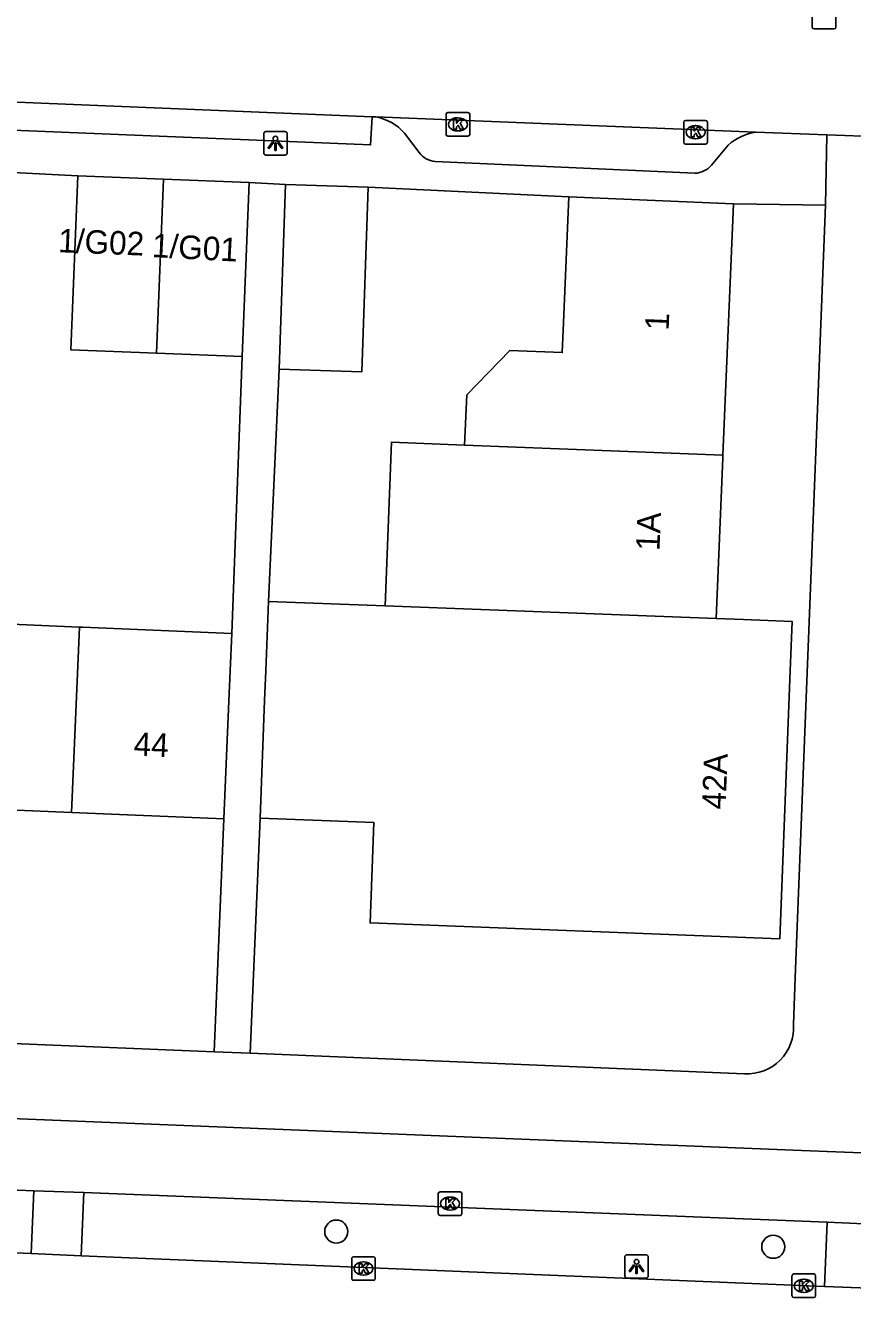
# Model space of a CAD drawing. Extents: x 160732 to 162105, y 387428 to 388479.
# Drawn here: x 161213.7 to 161248.8, y 387473.4 to 387527.4 of the extents above; entities that cross this region are included whole.
import ezdxf

# ---------------------------------------------------------------- set-up
doc = ezdxf.new("R2010")
doc.units = 0
for name, color, linetype in [('IMGEO_Boom', 7, 'Continuous'), ('IMGEO_Fietspad_open', 7, 'Continuous'), ('IMGEO_Kolk', 7, 'Continuous'), ('IMGEO_Lichtpunt', 7, 'Continuous'), ('IMGEO_Muur', 7, 'Continuous'), ('IMGEO_Pand', 7, 'Continuous'), ('IMGEO_Pand_nummerreeks', 7, 'Continuous'), ('IMGEO_Rijbaan_lokaal_gesloten', 7, 'Continuous'), ('IMGEO_Rijbaan_lokaal_open', 7, 'Continuous'), ('IMGEO_Voetpad_open', 7, 'Continuous')]:
    doc.layers.add(name, color=color, linetype=linetype)

msp = doc.modelspace()

# ---------------------------------------------------------------- linework, layer by layer
at = {"layer": 'IMGEO_Boom'}
for centre in [(161226.862, 387476.19), (161245.405, 387475.542)]:
    msp.add_circle(centre, 0.489, dxfattribs=at)
at = {"layer": 'IMGEO_Fietspad_open'}
for points in [[(161134.151, 387484.191), (161246.605, 387479.634), (161252.434, 387479.398)], [(161214.028, 387477.925), (161190.637, 387478.875)], [(161216.159, 387477.843), (161214.028, 387477.925)], [(161247.692, 387476.584), (161216.159, 387477.843)], [(161249.589, 387476.508), (161247.692, 387476.584)]]:
    msp.add_lwpolyline(points, dxfattribs=at)
at = {"layer": 'IMGEO_Kolk'}
for p, q in [((161247.06, 387527.319), (161247.06, 387528.171)), ((161248.061, 387528.171), (161248.061, 387527.319)), ((161247.987, 387527.245), (161247.135, 387527.245)), ((161231.524, 387522.766), (161231.524, 387523.618)), ((161231.599, 387523.692), (161232.451, 387523.692)), ((161232.525, 387523.618), (161232.525, 387522.766)), ((161232.012, 387523.472), (161232.037, 387523.472)), ((161241.607, 387522.431), (161241.607, 387523.283)), ((161241.682, 387523.357), (161242.534, 387523.357)), ((161242.095, 387523.137), (161242.12, 387523.137)), ((161242.608, 387523.283), (161242.608, 387522.431)), ((161232.451, 387522.692), (161231.599, 387522.692)), ((161232.035, 387522.912), (161232.01, 387522.912)), ((161242.118, 387522.577), (161242.093, 387522.577)), ((161242.534, 387522.357), (161241.682, 387522.357)), ((161231.192, 387476.95), (161231.192, 387477.802)), ((161231.267, 387477.876), (161232.119, 387477.876)), ((161232.193, 387477.802), (161232.193, 387476.95)), ((161231.68, 387477.656), (161231.705, 387477.656)), ((161232.119, 387476.876), (161231.267, 387476.876)), ((161231.703, 387477.096), (161231.678, 387477.096)), ((161227.518, 387474.193), (161227.518, 387475.045)), ((161227.593, 387475.119), (161228.445, 387475.119)), ((161228.519, 387475.045), (161228.519, 387474.193)), ((161228.006, 387474.899), (161228.031, 387474.899)), ((161228.445, 387474.119), (161227.593, 387474.119)), ((161228.029, 387474.339), (161228.004, 387474.339)), ((161246.2, 387473.462), (161246.2, 387474.314)), ((161246.275, 387474.388), (161247.127, 387474.388)), ((161246.688, 387474.168), (161246.713, 387474.168)), ((161247.201, 387474.314), (161247.201, 387473.462)), ((161247.127, 387473.388), (161246.275, 387473.388)), ((161246.711, 387473.608), (161246.686, 387473.608))]:
    msp.add_line(p, q, dxfattribs=at)
for points in [[(161247.06, 387527.319), (161247.06, 387528.171)], [(161248.061, 387528.171), (161248.061, 387527.319)], [(161247.987, 387527.245), (161247.135, 387527.245)], [(161231.524, 387522.766), (161231.524, 387523.618)], [(161231.599, 387523.692), (161232.451, 387523.692)], [(161232.525, 387523.618), (161232.525, 387522.766)], [(161231.845, 387523.392), (161231.968, 387523.392), (161231.968, 387523.241), (161232.098, 387523.392), (161232.262, 387523.392), (161232.116, 387523.241), (161232.269, 387522.992), (161232.117, 387522.992), (161232.032, 387523.156), (161231.968, 387523.089), (161231.968, 387522.992), (161231.845, 387522.992), (161231.845, 387523.392)], [(161241.607, 387522.431), (161241.607, 387523.283)], [(161241.682, 387523.357), (161242.534, 387523.357)], [(161242.608, 387523.283), (161242.608, 387522.431)], [(161232.451, 387522.692), (161231.599, 387522.692)], [(161241.928, 387523.057), (161242.051, 387523.057), (161242.051, 387522.906), (161242.181, 387523.057), (161242.345, 387523.057), (161242.199, 387522.906), (161242.352, 387522.657), (161242.2, 387522.657), (161242.115, 387522.821), (161242.051, 387522.754), (161242.051, 387522.657), (161241.928, 387522.657), (161241.928, 387523.057)], [(161242.534, 387522.357), (161241.682, 387522.357)], [(161231.192, 387476.95), (161231.192, 387477.802)], [(161231.267, 387477.876), (161232.119, 387477.876)], [(161232.193, 387477.802), (161232.193, 387476.95)], [(161231.513, 387477.576), (161231.636, 387477.576), (161231.636, 387477.425), (161231.766, 387477.576), (161231.93, 387477.576), (161231.784, 387477.425), (161231.937, 387477.176), (161231.785, 387477.176), (161231.7, 387477.34), (161231.636, 387477.273), (161231.636, 387477.176), (161231.513, 387477.176), (161231.513, 387477.576)], [(161232.119, 387476.876), (161231.267, 387476.876)], [(161227.518, 387474.193), (161227.518, 387475.045)], [(161227.593, 387475.119), (161228.445, 387475.119)], [(161228.519, 387475.045), (161228.519, 387474.193)], [(161227.839, 387474.819), (161227.962, 387474.819), (161227.962, 387474.668), (161228.092, 387474.819), (161228.256, 387474.819), (161228.11, 387474.668), (161228.263, 387474.419), (161228.111, 387474.419), (161228.026, 387474.583), (161227.962, 387474.516), (161227.962, 387474.419), (161227.839, 387474.419), (161227.839, 387474.819)], [(161228.445, 387474.119), (161227.593, 387474.119)], [(161246.2, 387473.462), (161246.2, 387474.314)], [(161246.275, 387474.388), (161247.127, 387474.388)], [(161246.521, 387474.088), (161246.644, 387474.088), (161246.644, 387473.937), (161246.774, 387474.088), (161246.938, 387474.088), (161246.792, 387473.937), (161246.945, 387473.688), (161246.793, 387473.688), (161246.708, 387473.852), (161246.644, 387473.785), (161246.644, 387473.688), (161246.521, 387473.688), (161246.521, 387474.088)], [(161247.201, 387474.314), (161247.201, 387473.462)], [(161247.127, 387473.388), (161246.275, 387473.388)]]:
    msp.add_lwpolyline(points, dxfattribs=at)
for centre, start, end in [((161247.137, 387527.321), 181.552, 268.448), ((161247.137, 387527.321), 181.552, 268.448), ((161247.985, 387527.321), 271.552, 358.448), ((161247.985, 387527.321), 271.552, 358.448), ((161231.601, 387523.616), 91.552, 178.448), ((161231.601, 387523.616), 91.552, 178.448), ((161232.449, 387523.616), 1.552, 88.448), ((161232.449, 387523.616), 1.552, 88.448), ((161241.684, 387523.281), 91.552, 178.448), ((161241.684, 387523.281), 91.552, 178.448), ((161242.532, 387523.281), 1.552, 88.448), ((161242.532, 387523.281), 1.552, 88.448), ((161231.601, 387522.768), 181.552, 268.448), ((161231.601, 387522.768), 181.552, 268.448), ((161232.449, 387522.768), 271.552, 358.448), ((161232.449, 387522.768), 271.552, 358.448), ((161241.684, 387522.433), 181.552, 268.448), ((161241.684, 387522.433), 181.552, 268.448), ((161242.532, 387522.433), 271.552, 358.448), ((161242.532, 387522.433), 271.552, 358.448), ((161231.269, 387477.8), 91.552, 178.448), ((161231.269, 387477.8), 91.552, 178.448), ((161232.117, 387477.8), 1.552, 88.448), ((161232.117, 387477.8), 1.552, 88.448), ((161231.269, 387476.952), 181.552, 268.448), ((161231.269, 387476.952), 181.552, 268.448), ((161232.117, 387476.952), 271.552, 358.448), ((161232.117, 387476.952), 271.552, 358.448), ((161227.595, 387475.043), 91.552, 178.448), ((161227.595, 387475.043), 91.552, 178.448), ((161228.443, 387475.043), 1.552, 88.448), ((161228.443, 387475.043), 1.552, 88.448), ((161227.595, 387474.195), 181.552, 268.448), ((161227.595, 387474.195), 181.552, 268.448), ((161228.443, 387474.195), 271.552, 358.448), ((161228.443, 387474.195), 271.552, 358.448), ((161246.277, 387474.312), 91.552, 178.448), ((161246.277, 387474.312), 91.552, 178.448), ((161247.125, 387474.312), 1.552, 88.448), ((161247.125, 387474.312), 1.552, 88.448), ((161246.277, 387473.464), 181.552, 268.448), ((161246.277, 387473.464), 181.552, 268.448), ((161247.125, 387473.464), 271.552, 358.448), ((161247.125, 387473.464), 271.552, 358.448)]:
    msp.add_arc(centre, 0.0765, start, end, dxfattribs=at)
for centre, major_axis, ratio, start_param, end_param in [((161232.011, 387523.192), (-0.387, 0.002), 0.722429, 4.712389, 7.853982), ((161232.036, 387523.192), (-0.39, 0.002), 0.717154, 1.570796, 4.712389), ((161242.094, 387522.857), (-0.387, 0.002), 0.722429, 4.712389, 7.853982), ((161242.119, 387522.857), (-0.39, 0.002), 0.717154, 1.570796, 4.712389), ((161231.679, 387477.376), (-0.387, 0.002), 0.722429, 4.712389, 7.853982), ((161231.704, 387477.376), (-0.39, 0.002), 0.717154, 1.570796, 4.712389), ((161228.005, 387474.619), (-0.387, 0.002), 0.722429, 4.712389, 7.853982), ((161228.03, 387474.619), (-0.39, 0.002), 0.717154, 1.570796, 4.712389), ((161246.687, 387473.888), (-0.387, 0.002), 0.722429, 4.712389, 7.853982), ((161246.712, 387473.888), (-0.39, 0.002), 0.717154, 1.570796, 4.712389)]:
    msp.add_ellipse(centre, major_axis=major_axis, ratio=ratio, start_param=start_param, end_param=end_param, dxfattribs=at)
at = {"layer": 'IMGEO_Lichtpunt'}
for p, q in [((161223.785, 387522.79), (161223.785, 387521.983)), ((161223.785, 387522.79), (161223.785, 387521.983)), ((161224.687, 387522.885), (161223.879, 387522.885)), ((161224.687, 387522.885), (161223.879, 387522.885)), ((161224.781, 387521.983), (161224.781, 387522.79)), ((161224.781, 387521.983), (161224.781, 387522.79)), ((161223.879, 387521.889), (161224.687, 387521.889)), ((161223.879, 387521.889), (161224.687, 387521.889)), ((161239.105, 387475.112), (161239.105, 387474.305)), ((161239.105, 387475.112), (161239.105, 387474.305)), ((161240.007, 387475.207), (161239.199, 387475.207)), ((161240.007, 387475.207), (161239.199, 387475.207)), ((161240.101, 387474.305), (161240.101, 387475.112)), ((161240.101, 387474.305), (161240.101, 387475.112)), ((161239.199, 387474.211), (161240.007, 387474.211)), ((161239.199, 387474.211), (161240.007, 387474.211))]:
    msp.add_line(p, q, dxfattribs=at)
for points in [[(161224.159, 387522.454), (161224.198, 387522.426), (161224.01, 387522.164), (161223.972, 387522.191), (161224.159, 387522.454)], [(161224.261, 387522.406), (161224.308, 387522.406), (161224.308, 387522.084), (161224.261, 387522.084), (161224.261, 387522.406)], [(161224.371, 387522.426), (161224.409, 387522.453), (161224.596, 387522.191), (161224.557, 387522.163), (161224.371, 387522.426)], [(161239.479, 387474.776), (161239.518, 387474.748), (161239.33, 387474.486), (161239.292, 387474.513), (161239.479, 387474.776)], [(161239.581, 387474.728), (161239.628, 387474.728), (161239.628, 387474.406), (161239.581, 387474.406), (161239.581, 387474.728)], [(161239.691, 387474.748), (161239.729, 387474.775), (161239.916, 387474.513), (161239.877, 387474.485), (161239.691, 387474.748)]]:
    msp.add_lwpolyline(points, dxfattribs=at)
for centre in [(161224.284, 387522.588), (161239.604, 387474.91)]:
    msp.add_circle(centre, 0.0994, dxfattribs=at)
for centre, start, end in [((161223.879, 387522.79), 90, 180), ((161223.879, 387522.79), 90, 180), ((161224.687, 387522.79), 0, 90), ((161224.687, 387522.79), 0, 90), ((161223.879, 387521.983), 180, 270), ((161223.879, 387521.983), 180, 270), ((161224.687, 387521.983), 270, 0), ((161224.687, 387521.983), 270, 360), ((161239.199, 387475.112), 90, 180), ((161239.199, 387475.112), 90, 180), ((161240.007, 387475.112), 0, 90), ((161240.007, 387475.112), 0, 90), ((161239.199, 387474.305), 180, 270), ((161239.199, 387474.305), 180, 270), ((161240.007, 387474.305), 270, 0), ((161240.007, 387474.305), 270, 360)]:
    msp.add_arc(centre, 0.0946, start, end, dxfattribs=at)
at = {"layer": 'IMGEO_Muur'}
msp.add_lwpolyline([(161228.212, 387520.523), (161236.726, 387520.113)], dxfattribs=at)
at = {"layer": 'IMGEO_Pand'}
for points in [[(161219.237, 387513.478), (161215.601, 387513.624), (161215.898, 387521.014)], [(161215.898, 387521.014), (161219.534, 387520.868)], [(161219.534, 387520.868), (161219.237, 387513.478)], [(161219.534, 387520.868), (161223.17, 387520.722)], [(161223.17, 387520.722), (161222.873, 387513.332)], [(161224.441, 387512.804), (161224.71, 387520.643)], [(161228.212, 387520.523), (161227.943, 387512.684), (161224.441, 387512.804)], [(161224.71, 387520.643), (161228.212, 387520.523)], [(161232.31, 387509.572), (161232.399, 387511.705), (161234.223, 387513.595), (161236.45, 387513.502), (161236.502, 387514.76), (161236.517, 387515.118), (161236.726, 387520.113)], [(161236.726, 387520.113), (161243.712, 387519.822)], [(161243.712, 387519.822), (161243.489, 387514.468), (161243.268, 387509.147)], [(161222.873, 387513.332), (161219.237, 387513.478)], [(161228.941, 387502.752), (161229.209, 387509.702), (161232.31, 387509.572)], [(161232.31, 387509.572), (161243.268, 387509.147)], [(161243.268, 387509.147), (161243.263, 387509.032), (161242.979, 387502.217)], [(161223.629, 387493.738), (161223.822, 387498.735), (161223.871, 387500), (161223.984, 387502.943)], [(161223.984, 387502.943), (161228.941, 387502.752)], [(161242.979, 387502.217), (161228.941, 387502.752)], [(161209.658, 387502.118), (161209.875, 387502.109), (161215.964, 387501.849)], [(161242.979, 387502.217), (161244.14, 387502.17), (161246.208, 387502.087), (161246.128, 387500), (161245.689, 387488.619), (161228.299, 387489.289), (161228.463, 387493.552), (161227.717, 387493.581), (161223.629, 387493.738)], [(161215.629, 387493.984), (161215.964, 387501.849)], [(161215.964, 387501.849), (161216.093, 387501.843), (161222.433, 387501.573)], [(161222.433, 387501.573), (161222.366, 387500), (161222.311, 387498.704), (161222.097, 387493.708)], [(161215.629, 387493.984), (161209.324, 387494.253)], [(161222.097, 387493.708), (161215.629, 387493.984)]]:
    msp.add_lwpolyline(points, dxfattribs=at)
at = {"layer": 'IMGEO_Rijbaan_lokaal_gesloten'}
for points in [[(161213.915, 387475.253), (161190.553, 387476.218)], [(161216.043, 387475.164), (161213.915, 387475.253)], [(161247.58, 387473.86), (161216.043, 387475.164)], [(161249.477, 387473.782), (161247.58, 387473.86)]]:
    msp.add_lwpolyline(points, dxfattribs=at)
at = {"layer": 'IMGEO_Rijbaan_lokaal_open'}
for points in [[(161185.563, 387525.285), (161228.389, 387523.514)], [(161228.548, 387523.509), (161228.389, 387523.514)], [(161244.661, 387522.856), (161228.548, 387523.509)], [(161247.682, 387522.742), (161244.661, 387522.856)], [(161252.229, 387522.571), (161247.682, 387522.742)]]:
    msp.add_lwpolyline(points, dxfattribs=at)
at = {"layer": 'IMGEO_Voetpad_open'}
for points in [[(161228.389, 387523.514), (161228.32, 387522.321), (161185.519, 387524.08), (161185.563, 387525.285)], [(161230.388, 387521.991), (161229.752, 387522.823)], [(161247.623, 387519.76), (161247.682, 387522.742)], [(161243.485, 387522.311), (161242.784, 387521.462)], [(161242.075, 387521.116), (161231.065, 387521.615)], [(161215.898, 387521.014), (161213.15, 387521.148)], [(161224.71, 387520.643), (161223.17, 387520.722)], [(161236.726, 387520.113), (161228.212, 387520.523)], [(161247.623, 387519.76), (161243.712, 387519.822)], [(161246.261, 387484.984), (161246.339, 387486.968), (161246.93, 387502.077), (161247.623, 387519.76)], [(161222.873, 387513.332), (161222.433, 387501.573)], [(161223.984, 387502.943), (161224.441, 387512.804)], [(161222.097, 387493.708), (161221.687, 387483.819)], [(161223.215, 387483.756), (161223.629, 387493.738)], [(161184.131, 387485.375), (161221.687, 387483.819)], [(161221.687, 387483.819), (161223.215, 387483.756)], [(161223.215, 387483.756), (161244.186, 387482.887)], [(161213.915, 387475.253), (161214.028, 387477.925)], [(161216.043, 387475.164), (161216.159, 387477.843)], [(161247.692, 387476.584), (161247.58, 387473.86)]]:
    msp.add_lwpolyline(points, dxfattribs=at)
for centre, radius, start, end in [((161228.154, 387521.418), 2.128, 41.3223, 79.3315), ((161244.98, 387520.627), 2.251, 98.1336, 131.5957), ((161231.123, 387522.518), 0.904, 215.6045, 266.3007), ((161242.039, 387522.09), 0.974, 272.1339, 319.8919), ((161244.299, 387484.85), 1.966, 266.696, 3.9083)]:
    msp.add_arc(centre, radius, start, end, dxfattribs=at)

# ---------------------------------------------------------------- texts
at = {"layer": 'IMGEO_Pand_nummerreeks'}
for s, rotation, p in [('1/G02', 357.7006, (161215.053, 387517.765)), ('1/G01', 356.9059, (161219.025, 387517.561)), ('1', 87.6183, (161240.965, 387514.428)), ('1A', 87.612, (161240.576, 387505.075)), ('44', 357.5573, (161218.249, 387496.394)), ('42A', 87.7932, (161243.379, 387494.095))]:
    msp.add_text(s, height=1, rotation=rotation, dxfattribs=at).set_placement(p)

doc.saveas('drawing.dxf')
